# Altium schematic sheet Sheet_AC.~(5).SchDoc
size A4
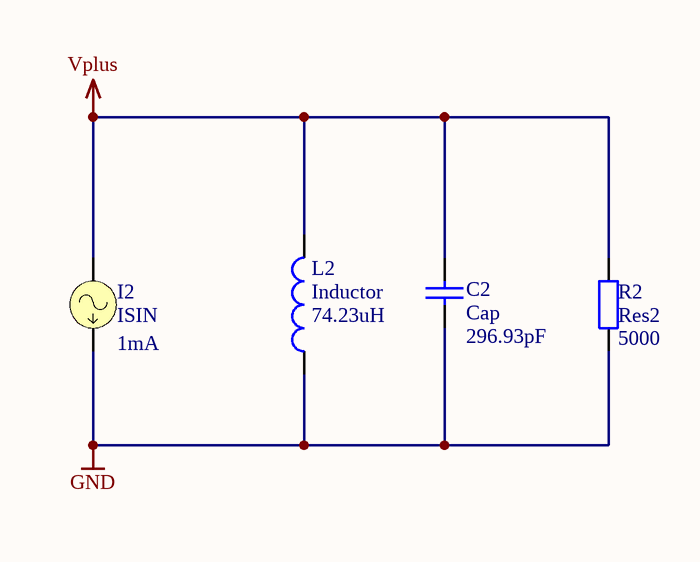
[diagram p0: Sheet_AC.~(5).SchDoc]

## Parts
C2  Cap  value 296.93pF  [RAD-0.3]
I2  ISIN  Amplitude: 1mA
L2  Inductor  value 74.23uH  [0402-A]
R2  Res2  value 5000  [AXIAL-0.4]

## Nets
GND: C2.1 I2.2 L2.1 R2.1
Vplus: C2.2 I2.1 L2.2 R2.2

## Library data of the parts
C2 = Cap: Capacitor
I2 = ISIN: Sinusoidal Current Source
L2 = Inductor: Code_IEC: 1005
R2 = Res2: Resistor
